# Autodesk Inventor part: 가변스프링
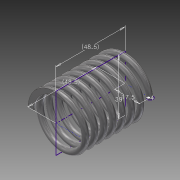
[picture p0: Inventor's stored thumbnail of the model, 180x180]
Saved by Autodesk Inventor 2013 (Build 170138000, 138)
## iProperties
Created: 2015-01
Part Number: 가변스프링
Material: 강철, 탄소
Document SubType Name: Modeling
Designer: Administrator
Density: 7.87 g/cm^3
Mass: 80.1301 g
Surface Area: 103.215 cm^2
Volume: 10.1817 cm^3
Author: Administrator
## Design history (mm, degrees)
sketch "스케치1"
  geometry: L1 (0, 0)-(17.5, 0); L2 (0, 0)-(0, -48.5); L3 (0, -48.5)-(17.5, -48.5); C1 r 2 at (17.5, 0)
  constraints: 6 end point, 2 perpendicular, 1 centre point, 1 horizontal
  dimensions: "d0" = 4 diameter of C1; "d1" = 17.5 distance of L1.start L1.end; "d2" = 48.5 distance of L1.start L2.end (derived)
feature "코일1" sketch "스케치1" pitch "d3" = 10; turns "d5" = 7.5; dims "d4" = 48.5 (= d2), "d6" = 0, angle "d7" = 90 deg, angle "d8" = 90 deg, "d9" = 0, "d10" = 0
sketch "스케치2"
  geometry: L1 (-48.5, 19.5)-(0, 19.5); L2 (0, 19.5)-(0, -19.5); L3 (0, -19.5)-(-48.5, -19.5); L4 (-48.5, -19.5)-(-48.5, 19.5); 2 further points
  constraints: 8 end point, 2 parallel, 1 coincident, 1 horizontal, 1 midpoint, 1 perpendicular
  dimensions: "d11" = 39 distance of L1.end L2.end; "d13" = 48.5 distance of L1.start L1.end (derived)
extrude "돌출1" sketch "스케치2" stored distance "d14" = 10; taper "d15" = 0 deg
node "솔리드1"
